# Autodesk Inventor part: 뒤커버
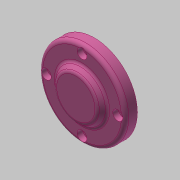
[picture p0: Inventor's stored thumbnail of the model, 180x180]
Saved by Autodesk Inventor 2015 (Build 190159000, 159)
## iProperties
Created: 2017-08
Part Number: 뒤커버
Material: 알루미늄 6061
Document SubType Name: Modeling
Designer: mduedu
Density: 2.71 g/cm^3
Appearance: 분홍색
Mass: 99.1179 g
Surface Area: 135.95 cm^2
Volume: 36.5749 cm^3
Author: mduedu
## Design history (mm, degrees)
sketch "스케치1"
  geometry: C1 r 35 at (0, 0); 1 further point
  constraints: 1 centre point, 1 coincident
  dimensions: "d0" = 70 diameter of C1
extrude "돌출1" new body sketch "스케치1" distance "d1" = 10; taper "d2" = 0 deg
sketch "스케치2"
  geometry: C1 r 21 at (0, 0); 1 further point
  constraints: 1 centre point, 1 coincident
  dimensions: "d3" = 42 diameter of C1
node "작업 평면1"
sketch "스케치3"
  geometry: C1 r 17 at (0, 0); 1 further point
  constraints: 1 centre point, 1 coincident
  dimensions: "d5" = 34 diameter of C1
feature "로프트1" sketch "스케치3" dims "d6" = 0, "d7" = 90 deg, "d8" = 0, "d9" = 90 deg
sketch "스케치4"
  geometry: C1 r 24 at (0, 0); 1 further point
  constraints: 1 centre point, 1 coincident
  dimensions: "d65" = 48 diameter of C1
extrude "돌출2" join sketch "스케치4" distance "d10" = 8; taper "d11" = 0 deg
hole "구멍1" diameter "d14" = 40; stored, may be unused: countersink angle "d18" = 90 deg, drill point angle "d20" = 0 deg; dims "d15" = 6, "d16" = 4, "d17" = 2, "d19" = 12, "d66" = 10, "d67" = 10
hole "구멍2" diameter "d23" = 34; stored, may be unused: countersink angle "d27" = 90 deg, drill point angle "d29" = 0 deg; dims "d24" = 6, "d25" = 4, "d26" = 2, "d28" = 6, "d62" = 10, "d63" = 10
chamfer "모따기1" distance "d39" = 1; stored, may be unused: second distance "d40" = 2, angle "d41" = 45 deg
fillet "모깎기1" dims "d42" = 0.3
fillet "모깎기2" dims "d43" = 3
sketch "스케치5" dims "d44" = 58
  geometry: 6 further points
  constraints: 2 vertical alignment, 1 coincident, 7 other
  dimensions: "d47" = 360 deg dimension on point (0, 0) point (0, 29) (derived)
sketch "스케치6" dims "d64" = 58 (derived)
  geometry: 6 further points
  constraints: 1 coincident, 1 vertical alignment, 6 other
hole "구멍4" sketch "스케치6" at (0, 29), (-29, 0), (29, 0), (0, -29) diameter "d49" = 4.5; stored, may be unused: countersink angle "d53" = 90 deg, drill point angle "d55" = 0 deg; dims "d50" = 6, "d51" = 8, "d52" = 4.6, "d54" = 8
fillet "모깎기3" dims "d56" = 3
fillet "모깎기4" dims "d57" = 3
fillet "모깎기5" dims "d58" = 3
node "솔리드1"
other parameters: "d4" = 5
